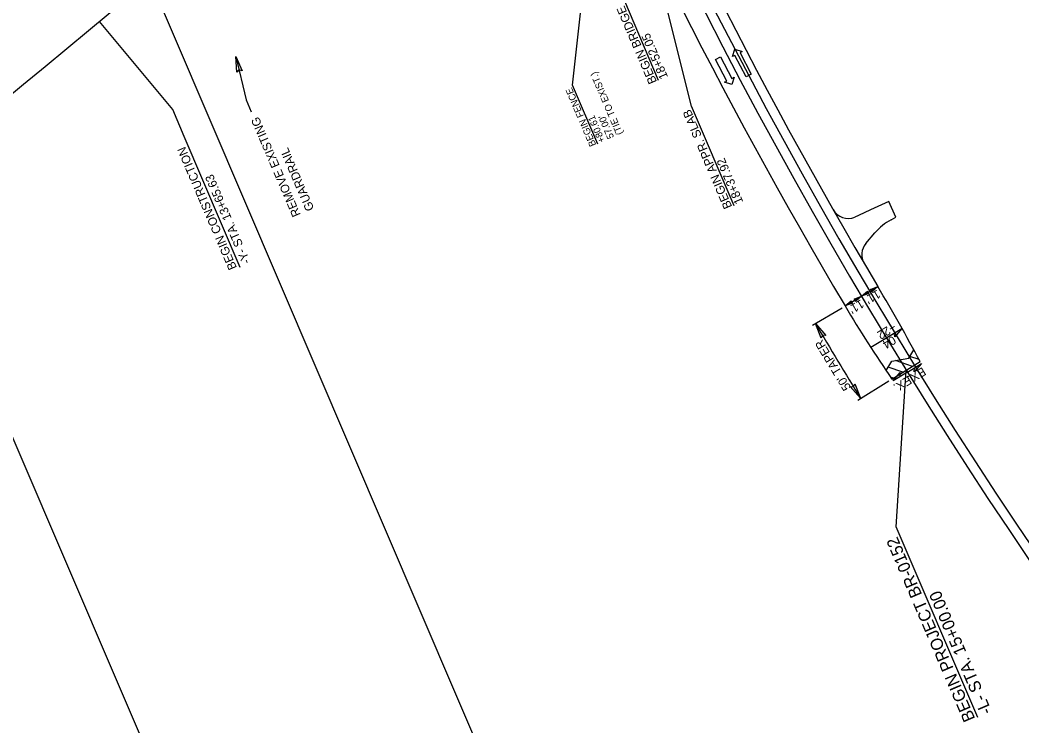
# Model space of a CAD drawing. Extents: x 1550950 to 1552827, y 809595 to 812050.
# Drawn here: x 1551529 to 1552108, y 810109 to 810517 of the extents above; entities that cross this region are included whole.
import ezdxf

# ---------------------------------------------------------------- set-up
doc = ezdxf.new("R2010")
doc.units = 0
for name, color, linetype in [('3D Cell Connection Region', 7, 'Continuous'), ('_CIVIL_CONSTRUCTION', 7, 'Continuous'), ('Catch Basin Box 24 Dia-Bottom CELL', 7, 'Continuous'), ('Draft_Plan_Labels', 7, 'Continuous'), ('Drop Inlet Grate 2 Narrow Slot and Flat Grates 840 29 36 Dia BD Apron CELL', 7, 'Continuous'), ('Drop Inlet Grate 2 Narrow Slot and Flat Grates 840 29 36 Dia BD Apron-Top CELL', 7, 'Continuous'), ('Drop Inlet Grate 2 Narrow Slot and Flat Grates 840 29 36 Dia BD CELL', 7, 'Continuous'), ('Drop Inlet Grate 2 Narrow Slot and Flat Grates 840 29 36 Dia TB-Top CELL', 7, 'Continuous'), ('Drop Inlet Grate 840 16 CELL', 7, 'Continuous'), ('P_HYD_Ditch_Flow_Arrow', 7, 'Continuous'), ('P_HYD_Drop_Inlet_Box_Traffic_Bearing_840_35-Bottom_CELL', 7, 'Continuous'), ('P_HYD_Pipe_RCP_15in_Class_III', 7, 'Continuous'), ('P_HYD_Pipe_RCP_Class_III', 7, 'Continuous'), ('V Ditch Special Lateral with PSRM Detail CELL', 7, 'Continuous')]:
    doc.layers.add(name, color=color, linetype=linetype)

msp = doc.modelspace()

# ---------------------------------------------------------------- linework, layer by layer
at = {"layer": '3D Cell Connection Region'}
for p, q in [((1552020.59, 810327.61), (1552038.65, 810338.55)), ((1552041.81, 810313.22), (1552049.86, 810318.19)), ((1552041.81, 810313.22), (1552033.55, 810308.13))]:
    msp.add_line(p, q, dxfattribs=at)
at = {"layer": '_CIVIL_CONSTRUCTION'}
for p, q in [((1552015.25, 810357.12), (1552024.71, 810362.73)), ((1552005.79, 810351.51), (1552015.25, 810357.12)), ((1551986.93, 810340.32), (1552004.07, 810350.49)), ((1552013.09, 810297.05), (1552031.16, 810308.19))]:
    msp.add_line(p, q, dxfattribs=at)
at = {"layer": 'Draft_Plan_Labels'}
for points in [[(1551898.07, 810481.9), (1551878.45, 810527.75), (1551874.88, 810624.42)], [(1551941.7, 810409.34), (1551916.99, 810467.06), (1551880.83, 810611.6)], [(1551862.89, 810445.08), (1551848.32, 810479.12), (1551854.4, 810534.8)], [(1551653.69, 810495.73), (1551659.77, 810470.62), (1551662.73, 810463.69)], [(1551656.3, 810373.69), (1551623.9, 810449.38), (1551617.33, 810464.99)], [(1552082.46, 810113.55), (1552035.29, 810223.74), (1552041.13, 810314.33)]]:
    msp.add_lwpolyline(points, dxfattribs=at)
at = {"layer": 'Drop Inlet Grate 2 Narrow Slot and Flat Grates 840 29 36 Dia BD Apron CELL'}
for p, q in [((1552044.71, 810316.54), (1552034.86, 810319.93)), ((1552048.52, 810320.52), (1552043.25, 810322.33)), ((1552039.21, 810313.15), (1552030.69, 810316.07)), ((1552033.7, 810309.75), (1552032.13, 810310.29))]:
    msp.add_line(p, q, dxfattribs=at)
msp.add_lwpolyline([(1552029.49, 810314.17), (1552032.9, 810319.59), (1552042.6, 810321.25), (1552045.52, 810326.09)], dxfattribs=at)
at = {"layer": 'Drop Inlet Grate 2 Narrow Slot and Flat Grates 840 29 36 Dia BD Apron-Top CELL'}
msp.add_line((1551617.33, 810464.99), (1551574.97, 810515.9), dxfattribs=at)
at = {"layer": 'Drop Inlet Grate 2 Narrow Slot and Flat Grates 840 29 36 Dia BD CELL'}
msp.add_lwpolyline([(1551862.14, 809937.08), (1551252.51, 811362.16), (1551737.49, 811569.62), (1552347.13, 810144.54)], close=True, dxfattribs=at)
msp.add_arc((1554524.17, 811845.14), 2911.5, 194.24112, 221.47505, dxfattribs=at)
at = {"layer": 'Drop Inlet Grate 2 Narrow Slot and Flat Grates 840 29 36 Dia TB-Top CELL'}
for points in [[(1551654.3, 810486.62), (1551653.69, 810495.73), (1551657.37, 810487.31), (1551655.55, 810488.05)], [(1552019.52, 810358.75), (1552015.25, 810357.12), (1552018.74, 810360.11), (1552018.65, 810359.13)], [(1552020.45, 810361.1), (1552024.71, 810362.73), (1552021.23, 810359.73), (1552021.32, 810360.71)], [(1552010.06, 810353.13), (1552005.79, 810351.51), (1552009.28, 810354.5), (1552009.19, 810353.52)], [(1552010.99, 810355.49), (1552015.25, 810357.12), (1552011.77, 810354.12), (1552011.86, 810355.1)], [(1551991.9, 810332.8), (1551988.65, 810341.34), (1551994.64, 810334.37), (1551992.68, 810334.54)], [(1552011.39, 810306.57), (1552014.79, 810298.1), (1552008.68, 810304.96), (1552010.65, 810304.82)]]:
    msp.add_lwpolyline(points, close=True, dxfattribs=at)
at = {"layer": 'Drop Inlet Grate 840 16 CELL'}
for points in [[(1552038.65, 810338.55), (1552034.55, 810333.73), (1552034.69, 810336.16)], [(1552049.86, 810318.19), (1552045.8, 810313.34), (1552045.92, 810315.76)], [(1552033.55, 810308.13), (1552037.61, 810312.98), (1552037.49, 810310.55)]]:
    msp.add_lwpolyline(points, close=True, dxfattribs=at)
at = {"layer": 'P_HYD_Ditch_Flow_Arrow'}
msp.add_arc((1554524.17, 811845.14), 2917, 194.24112, 221.47505, dxfattribs=at)
at = {"layer": 'P_HYD_Drop_Inlet_Box_Traffic_Bearing_840_35-Bottom_CELL'}
msp.add_arc((1554524.17, 811845.14), 2947.94, 210.67194, 211.65404, dxfattribs=at)
at = {"layer": 'P_HYD_Pipe_RCP_15in_Class_III'}
msp.add_lwpolyline([(1552827.2, 810027.94), (1551961.46, 812050.44), (1550950.21, 811617.57), (1551815.95, 809595.07)], close=True, dxfattribs=at)
at = {"layer": 'P_HYD_Pipe_RCP_Class_III'}
for p, q in [((1551940.83, 810495.61), (1551942.12, 810499.83)), ((1551942.12, 810499.83), (1551946.42, 810498.52)), ((1551930.93, 810493.93), (1551933.86, 810495.46)), ((1551937.4, 810481.51), (1551930.93, 810493.93)), ((1551933.86, 810495.46), (1551940.33, 810483.04)), ((1551942.16, 810496.3), (1551940.83, 810495.61)), ((1551948.63, 810483.88), (1551942.16, 810496.3)), ((1551946.42, 810498.52), (1551945.09, 810497.82)), ((1551945.09, 810497.82), (1551951.56, 810485.41)), ((1551940.33, 810483.04), (1551941.66, 810483.73)), ((1551941.66, 810483.73), (1551940.37, 810479.51)), ((1551951.56, 810485.41), (1551948.63, 810483.88)), ((1551936.07, 810480.82), (1551937.4, 810481.51)), ((1551940.37, 810479.51), (1551936.07, 810480.82))]:
    msp.add_line(p, q, dxfattribs=at)
at = {"layer": 'V Ditch Special Lateral with PSRM Detail CELL'}
for p, q in [((1552035.03, 810402.73), (1552031.03, 810411.9)), ((1552013.47, 810403.71), (1552011.38, 810402.85)), ((1552032.38, 810401.31), (1552035.03, 810402.73)), ((1552017.76, 810387.6), (1552023.04, 810393.77)), ((1552032.86, 810309.24), (1552049.18, 810319.3))]:
    msp.add_line(p, q, dxfattribs=at)
msp.add_lwpolyline([(1552031.03, 810411.9), (1552020.39, 810407.11), (1552013.47, 810403.71)], dxfattribs=at)
for centre, radius, start, end in [((1554524.17, 811845.14), 2906, 194.24112, 210.67194), ((1554524.17, 811845.14), 2928, 194.24112, 210.67194), ((1544245.73, 819324.67), 11459.16, 307.933611, 313.133611), ((1552007.58, 810412.11), 10, 209.65875, 292.29958), ((1552048.07, 810372.34), 32.95, 118.43974, 139.42548), ((1552025.44, 810381.19), 10, 140.16629, 210.36504), ((1551064.58, 809793.28), 1116.3, 28.11322, 30.67194), ((1552636.71, 810725.7), 733.54, 210.67194, 214.59325)]:
    msp.add_arc(centre, radius, start, end, dxfattribs=at)

# ---------------------------------------------------------------- texts
at = {"layer": 'Catch Basin Box 24 Dia-Bottom CELL'}
for s, rotation, p in [('.04', 211.22191, (1552034.82, 810335.46)), ('EX.', 211.67961, (1552050.49, 810316.33)), ('EX.', 211.67961, (1552042.3, 810311.34))]:
    msp.add_text(s, height=5, rotation=rotation, dxfattribs=at).set_placement(p)
at = {"layer": 'Draft_Plan_Labels'}
for s, height, p in [('BEGIN BRIDGE', 5, (1551897.18, 810481.08)), ('18+52.05', 5, (1551903.61, 810483.84)), ('(TIE TO EXIST.)', 4, (1551877.54, 810451.27)), ('BEGIN FENCE', 4, (1551862.1, 810444.65)), ('BEGIN APPR. SLAB', 5, (1551940.63, 810408.88)), ('REMOVE EXISTING', 5, (1551691.34, 810404.26)), ('+80.61', 4, (1551867.25, 810446.86)), ("57.00'", 4, (1551872.4, 810449.06)), ('BEGIN CONSTRUCTION', 5, (1551654.48, 810373.62)), ('GUARDRAIL', 5, (1551699.16, 810407.6)), ('18+37.92', 5, (1551947.06, 810411.64)), ('-Y- STA. 13+65.63', 5, (1551662.29, 810376.96)), ('BEGIN PROJECT BR-0152', 7, (1552081.1, 810112.9)), ('-L- STA. 15+00.00', 7, (1552090.75, 810117.03))]:
    msp.add_text(s, height=height, rotation=113.1736, dxfattribs=at).set_placement(p)
at = {"layer": 'P_HYD_Drop_Inlet_Box_Traffic_Bearing_840_35-Bottom_CELL'}
for s, rotation, p in [("11'", 210.67194, (1552024.35, 810361.08)), ("11'", 210.67194, (1552014.89, 810355.47)), ('+22', 211.22191, (1552033.48, 810341.97)), ("50' TAPER", 121.15362, (1552009.4, 810304.37))]:
    msp.add_text(s, height=5, rotation=rotation, dxfattribs=at).set_placement(p)

doc.saveas('drawing.dxf')
